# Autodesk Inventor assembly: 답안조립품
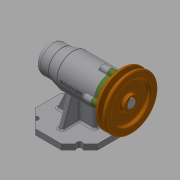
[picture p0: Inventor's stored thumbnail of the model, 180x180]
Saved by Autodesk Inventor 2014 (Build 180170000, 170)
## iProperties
Created: 2019-12
Part Number: 답안조립품
Document SubType Name: Assembly
Designer: kh
Author: kh
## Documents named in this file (12)
- C:\Users\kh\Desktop\491204V1040\답안조립품.iam
- C:\Users\kh\Desktop\491204V1040\본체.ipt
- C:\Users\kh\Desktop\491204V1040\Ű 5 x 5 x 16.ipt
- C:\Users\kh\Desktop\491204V1040\V벨트풀리.ipt
- C:\Users\kh\Desktop\491204V1040\멈춤나사 M3.ipt
- C:\Users\kh\Desktop\491204V1040\베어링 6004.ipt
- C:\Users\kh\Desktop\491204V1040\베어링 51202.ipt
- C:\Users\kh\Desktop\491204V1040\볼트 M4.ipt
- C:\Users\kh\Desktop\491204V1040\어댑터슬리브.ipt
- C:\Users\kh\Desktop\491204V1040\오일 실.ipt
- C:\Users\kh\Desktop\491204V1040\축.ipt
- C:\Users\kh\Desktop\491204V1040\커버.ipt
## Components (2 placed, 2 different names)
1. Ű 5 x 5 x 16:1 — Mate:11, Insert:3
2. V벨트풀리:1 — Mate:17, Mate:18, Angle:1
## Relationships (5: Mate 3, Insert 1, Angle 1)
- Mate:11: Ű 5 x 5 x 16:1
- Insert:3: Ű 5 x 5 x 16:1
- Mate:17: V벨트풀리:1
- Mate:18: V벨트풀리:1
- Angle:1: V벨트풀리:1
